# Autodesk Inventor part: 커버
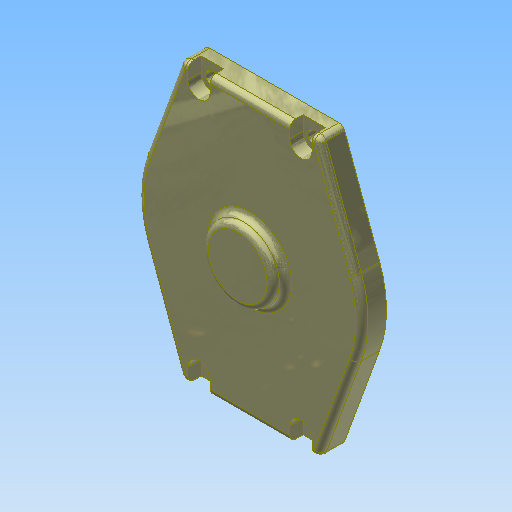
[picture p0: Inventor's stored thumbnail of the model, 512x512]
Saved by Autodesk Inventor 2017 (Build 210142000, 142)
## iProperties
Created: 2023-11
Part Number: 커버
Material: 알루미늄 6061
Document SubType Name: Modeling
Designer: mdu-01
Density: 1 g/cm^3
Appearance: 알루미늄 - 평지(1)
Author: mdu-01
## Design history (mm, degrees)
sketch "스케치1"
  geometry: L1 (-34.498, 66.026)-(-51.683, 18.811) reference; L2 (31.679, 68)-(-31.679, 68) reference; L3 (51.683, 18.811)-(34.498, 66.026) reference; L4 (-51.683, -18.811)-(-34.498, -66.026) reference; L5 (34.498, -66.026)-(51.683, -18.811) reference; L6 (-31.679, -68)-(31.679, -68) reference; C1 r 10 at (0, 0) reference; A1 r 3 centre (-31.679, 65) between (-31.679, 68) and (-34.498, 66.026) reference; A2 r 3 centre (31.679, 65) between (34.498, 66.026) and (31.679, 68) reference; A3 r 55 centre (0, 0) between (51.683, -18.811) and (51.683, 18.811) reference; A4 r 55 centre (0, 0) between (-51.683, 18.811) and (-51.683, -18.811) reference; A5 r 3 centre (-31.679, -65) between (-34.498, -66.026) and (-31.679, -68) reference; A6 r 3 centre (31.679, -65) between (31.679, -68) and (34.498, -66.026) reference; 1 further point
extrude "돌출1" new body sketch "스케치1" distance "d0" = 12; taper "d1" = 0 deg
sketch "스케치2"
  geometry: C1 r 10 at (0, 0) reference; 1 further point
extrude "돌출2" cut sketch "스케치2" distance "d2" = 10; taper "d3" = 0 deg
sketch "스케치3"
  geometry: C1 r 17.5 at (0, 0); 1 further point
  constraints: 1 centre point, 1 coincident
  dimensions: "d4" = 35 diameter of C1
extrude "돌출3" join sketch "스케치3" distance "d5" = 6; taper "d6" = 0 deg
fillet "모깎기1" dims "d7" = 3
sketch "스케치4"
  geometry: L1 (25, -61)-(-25, -61); L2 (-25, -61)-(-25, 61); L3 (-25, 61)-(25, 61); L4 (25, 61)-(25, -61); L5 (25, -61)-(-25, 61); L6 (-25, -61)-(25, 61); C1 r 2.458 at (-25, 61) reference; 1 further point
  constraints: 12 end point, 2 midpoint, 2 parallel, 1 coincident, 1 horizontal, 1 perpendicular
hole "구멍1" sketch "스케치4" at (-25, 61), (25, 61), (-25, -61), (25, -61) diameter "d8" = 6.6; stored, may be unused: countersink angle "d12" = 90 deg, drill point angle "d14" = 118 deg; dims "d9" = 6, "d10" = 11, "d11" = 6.6, "d13" = 8
sketch "스케치5"
  geometry: L1 (-30.5, 61)-(-19.5, 61); L2 (-19.5, 61)-(-19.5, 68); L3 (-19.5, 68)-(-30.5, 68); L4 (-30.5, 68)-(-30.5, 61); L5 (31.679, 68)-(-31.679, 68) reference; L6 (0, 0)-(0, 68); L7 (0, 0)-(-55, 0); L8 (19.5, 61)-(19.5, 68); L9 (19.5, 68)-(30.5, 68); L10 (30.5, 68)-(30.5, 61); L11 (30.5, 61)-(19.5, 61); L12 (19.5, -61)-(19.5, -68); L13 (19.5, -68)-(30.5, -68); L14 (30.5, -68)-(30.5, -61); L15 (30.5, -61)-(19.5, -61); L16 (-30.5, -68)-(-30.5, -61); L17 (-19.5, -68)-(-30.5, -68); L18 (-19.5, -61)-(-19.5, -68); L19 (-30.5, -61)-(-19.5, -61); A1 r 5.5 centre (-25, 61) between (-28.775, 65) and (-21.225, 65) reference; A2 r 55 centre (0, 0) between (-51.683, 18.811) and (-51.683, -18.811) reference
  constraints: 36 end point, 12 symmetric about line, 2 parallel, 2 point on circle, 2 tangent, 1 collinear, 1 horizontal, 1 midpoint, 1 perpendicular
extrude "돌출4" cut sketch "스케치5" stored distance "d15" = 6; taper "d16" = 0 deg
sketch "스케치6"
  geometry: L1 (10, 10)-(-10, 10) reference; L2 (7, 9.5)-(7, 2.044) reference; L3 (0, 10)-(0, 14.041); L4 (0, 14.041)-(7, 10); 1 further point
  constraints: 6 end point, 2 point on line, 1 midpoint, 1 parallel, 1 vertical, 2 other
  dimensions: "d17" = 60 deg angle of L3 L4
revolve "회전1" sketch "스케치6" stored, may be unused: angle "d18" = 90 deg
node "솔리드1"
node "참조1"
node "참조2"
node "참조3"
node "참조4"
node "참조5"
node "참조6"
node "참조7"
node "참조8"
node "참조9"
node "참조10"
node "참조11"
node "참조12"
node "참조13"
node "참조14"
